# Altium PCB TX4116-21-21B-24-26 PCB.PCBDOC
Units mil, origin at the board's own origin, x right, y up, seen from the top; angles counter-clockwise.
Board outline 1900 x 1181.1 mil, 2 copper layers (Top Layer, Bottom Layer); 23 components, 16 nets, 59 pads, 153 vias.
Unrouted connection lines stored in the file: 3.
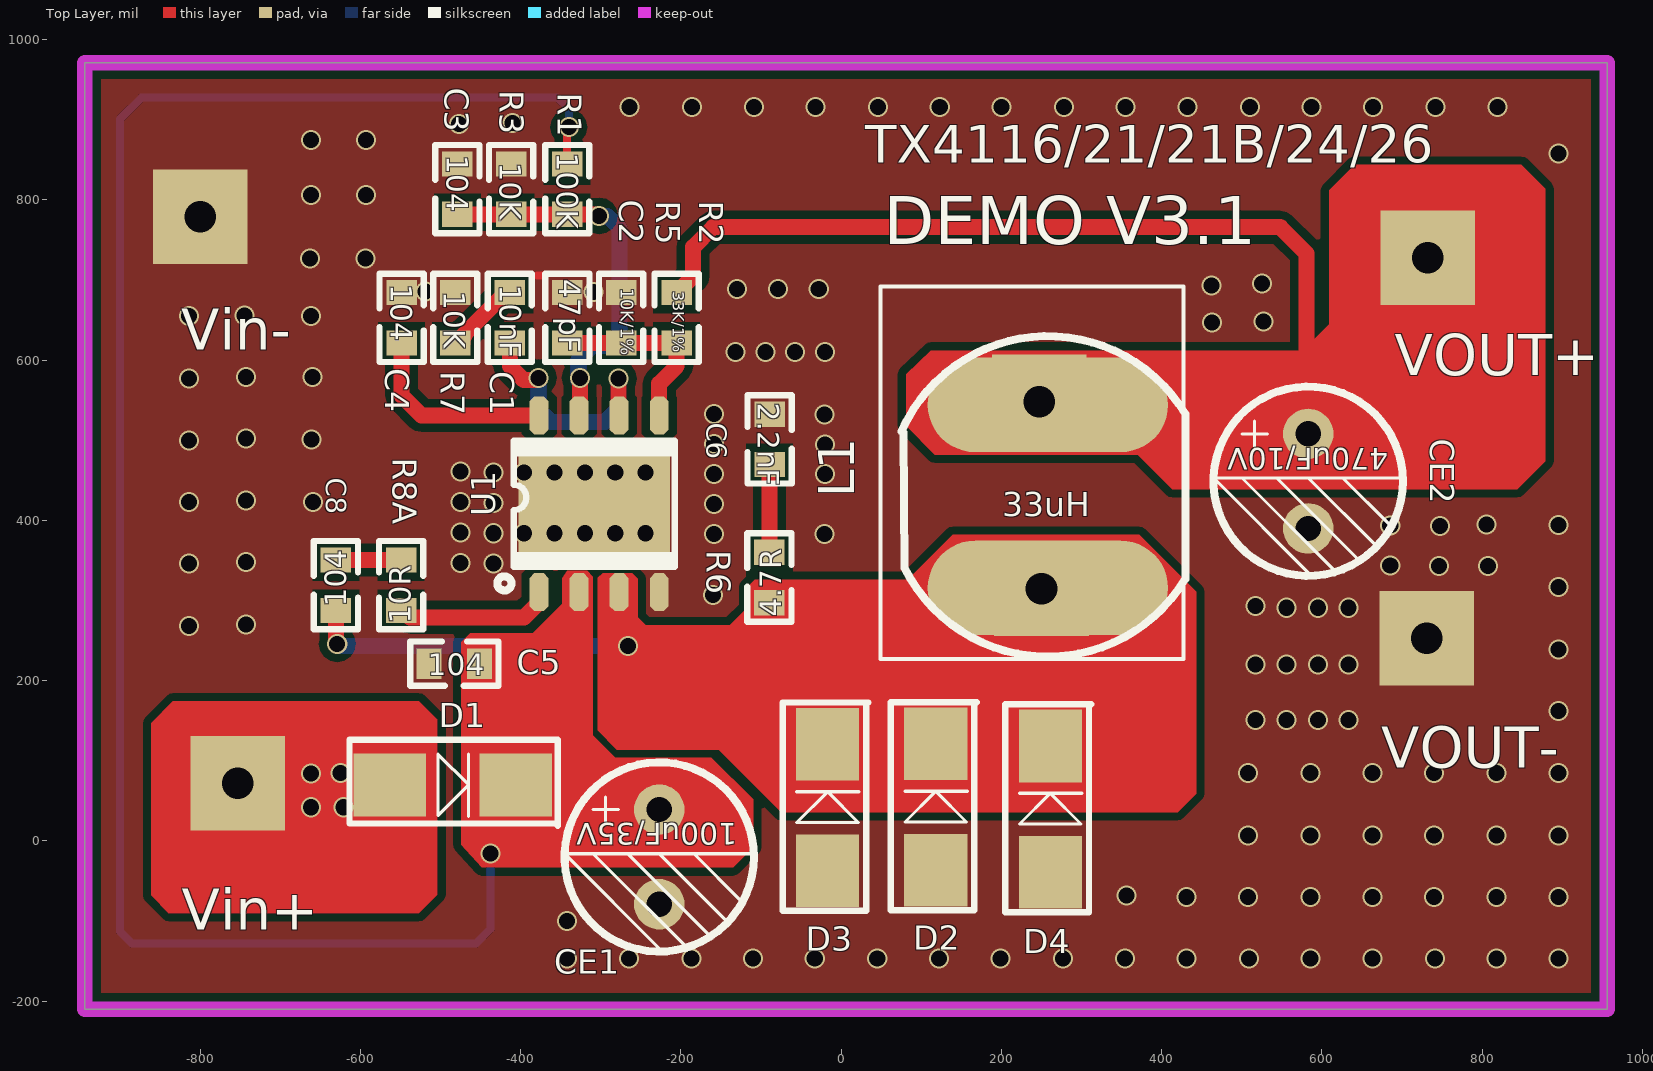
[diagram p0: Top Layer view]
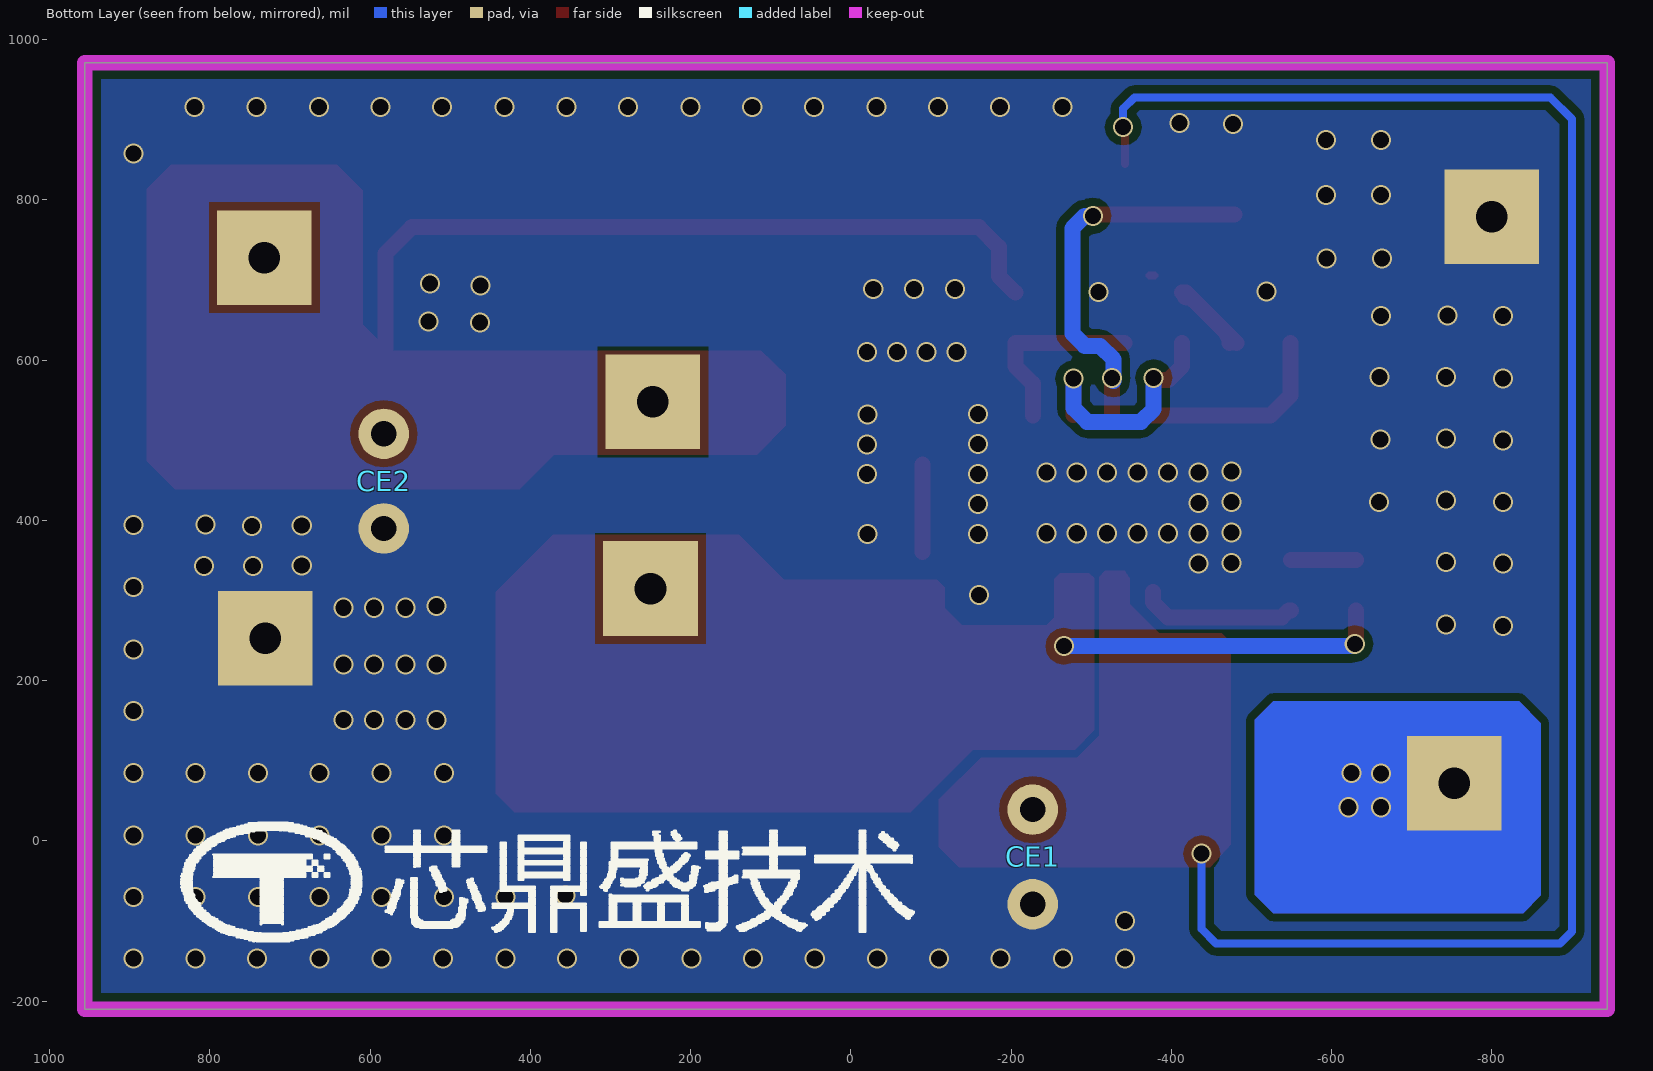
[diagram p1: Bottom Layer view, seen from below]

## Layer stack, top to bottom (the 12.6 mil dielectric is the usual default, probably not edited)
Top Layer: signal copper 1.4
Dielectric: dielectric 12.6, FR-4, Dk 4.8
Bottom Layer: signal copper 1.4

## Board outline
-944,-210 956,-210 956,971.1 -944,971.1

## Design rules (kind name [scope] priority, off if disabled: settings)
Clearance [All] p1: gap=10
PlaneConnect [All] p1: planeconnectstyle=NoConnect reliefexpansion=20 reliefentries=4 reliefconductorwidth=10 reliefairgap=10
PolygonConnect [All] p1: connectstyle=Direct reliefconductorwidth=0 reliefentries=4 polygonreliefangle="90 Angle"
RoutingVias [All] p1: holewidth=28 width=50 viastyle="Through Hole" minholewidth=28 minwidth=50 maxholewidth=28 maxwidth=50
SilkscreenOverComponentPads SilkToSolderMaskClearance [IsPad] p1: minsilkscreentomaskgap=10
SolderMaskExpansion [All] p1: expansion=4
TestPointUsage [All] p1: valid=0 allowmultiple=FALSE
Testpoint [All] p1: side=3 testpointundercomponent=TRUE minsize=40 maxsize=100 preferedsize=60 minholesize=0 maxholesize=40 preferedholesize=32 testpointgrid=1 style=297 order=0-112345678
Width [All] p1: maxlimit=100 minlimit=10 preferedwidth=10
22 further rules are at their usual default settings.

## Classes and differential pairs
component class 6321&8321&6322&8322: R6

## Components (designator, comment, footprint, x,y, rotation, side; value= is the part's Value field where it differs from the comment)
C1 "10nF" 0603 -419,648 r90 top (schematic designator C7)
C2 "47pF" 0603 -347,648 r90 top (schematic designator C6)
C3 "104" 0603 -484.35,808.66 r90 top (schematic designator C7)
C4 "104" 0603 -554,648 r90 top (schematic designator C7)
C5 "104" 0603 -478,216 r180 top (schematic designator C2)
C6 "2.2nF" 0603 -84,506 r270 top (schematic designator C5)
C8 "104" 0603 -636,314.31 r90 top (schematic designator C5)
CE1 "100uF/35V" C6 -239,-7 r270 bottom (schematic designator C1)
CE2 "470uF/10V" C6 571,462 r270 bottom (schematic designator C3)
D1 "Cap Semi" SMA -563.45,70 r0 top (schematic designator C4)
D2 "Cap Semi" SMA 118,-36.45 r90 top (schematic designator C4)
D3 "Cap Semi" SMA -17,-37 r90 top (schematic designator C4)
D4 "Cap Semi" SMA 261,-39 r90 top (schematic designator C4)
L1 "" CD105 258,430 r180 top
R1 "100K" 0603 -347.35,808.66 r90 top (schematic designator R3)
R2 "33K/1%" 0603 -200,657.69 r270 top (schematic designator R1)
R3 "10K" 0603 -417.35,808.66 r90 top
R5 "10K/1%" 0603 -280,648 r90 top (schematic designator R2)
R6 "4.7R" 0603 -95,324 r90 top (schematic designator R4)
R7 "10K" 0603 -487,648 r90 top (schematic designator R3)
R8A "10R" 0603 -544,324 r270 top (schematic designator R5)
U1 "TX4116/21/21B/24/26" ESOP-8A -312,413 r90 top
? "Comment" LOGO 722.33,-31 r180 bottom

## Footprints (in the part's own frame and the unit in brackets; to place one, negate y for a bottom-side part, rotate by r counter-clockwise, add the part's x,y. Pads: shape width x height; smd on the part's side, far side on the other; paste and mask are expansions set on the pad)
0603 [mm]
  rect 0.8x0.965 smd: 1(0.923,-0.136) 2(-0.677,-0.136)
  silkscreen extent -1.28,-0.84 1.52,0.56
C6 [mm]
  round 1.6 hole 0.8: 1(-1.17,-0.303) 2(1.83,-0.303)
CD105 [mm]
  oval 7.62x3 smd: 1(0,-2.9) 2(0,2.9)
  silkscreen extent -4.36,-5.08 4.64,5.08
ESOP-8A [mm]
  oct 1.2x0.6 smd: 1(-2.603,1.654) 2(-2.603,0.384) 3(-2.603,-0.886) 4(-2.603,-2.156) 5(2.997,-2.156) 6(2.997,-0.886) 7(2.997,0.384) 8(2.997,1.654)
  rect 3.048x4.8 smd: ""(0.2,-0.1)
  silkscreen extent -2.55,-2.65 2.2,2.98
LOGO [mil]
  silkscreen extent -113,-94 801,54
SMA [mm]
  rect 2.3x2 smd: 1(0,0) 2(4,0)
  silkscreen extent -1.28,-1.3 5.33,1.43

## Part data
C1 C2 C3 C4 C5 C6 C8: library part "Cap Semi", "Capacitor (Semiconductor SIM Model)"
CE1 CE2: library part "Cap Pol3", "Polarized Capacitor (Surface Mount)"
D1 D2 D3 D4: "Capacitor (Semiconductor SIM Model)"
L1: library part INDUCTOR
R1 R2 R3 R5 R6 R7 R8A: library part "Res Semi", "Semiconductor Resistor"
U1: library part PL6321

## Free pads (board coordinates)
  rect 118.11x118.11 hole 39.37: 0(-800,779) 0(-753,72) 0(247,548) 0(250,315) 0(731,253) 0(732,728)
  round 70.87 hole 39.37: 0(247,548) 1(250,315)

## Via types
v1: diameter 25, hole 20, Top Layer to Bottom Layer, tented both sides, 152 vias
v2: diameter 25/25 (per signal layer), hole 20, Top Layer to Bottom Layer, tented both sides, 1 vias

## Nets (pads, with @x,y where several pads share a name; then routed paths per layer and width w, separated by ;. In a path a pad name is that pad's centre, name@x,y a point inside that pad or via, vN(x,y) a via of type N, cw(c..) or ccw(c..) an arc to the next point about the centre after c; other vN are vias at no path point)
12V: D1.1 pad.0@-753,72
  other v1: -662,42 -621,42 -662,84 -625,85
EN: C3.2 R1.2 R3.2 U1.7 | length 475.8
  Top Layer w20: C3.2 R3.2 R1.2 v1@-304.01,782.01 ; U1.7@-326,532.11 v1(-326,578)
  Bottom Layer w20: v1@-328,574 -328,578 -328,601 -311,618 -292,618 -276.5,633.5 -276.5,764.5 -292,780 v1(-302,780)
GND: C2.1 C3.1 C4.1 C5.1 C6.2 CE1.2 CE2.2 D2.1 D3.1 D4.1 pad.0@731,253 pad.0@-800,779 R3.1 R5.1 R7.1 U1. U1.4 | length 6.3
  Top Layer w10: -379.35,706 -373,706
  other v1: -342,-147 -265,-147 -187,-147 -110,-147 -33,-147 45,-147 122,-147 199,-147 277,-147 354,-147 431,-147 509,-147 586,-147 663,-147 741,-147 818,-147 895,-147 -342,-100 431,-70 508,-70 586,-70 663,-70 740,-70 818,-70 895,-70 356,-68 508,7 586,7 663,7 740,7 818,7 895,7 508,85 586,85 663,85 740,85 818,85 895,85 517,151 556,151 595,151 633,151 895,162 517,220 556,220 595,220 633,220 895,239 -814,268 -743,270 556,291 595,291 633,291 517,293 -160,307 895,317 746.29,342.89 807.29,342.89 685.29,343.89 -814,346 -434,346 -475,347 -743,348 -159,383 -21,383 -434,384 -396,384 -358,384 -320,384 -282,384 -244,384 -475,385 747.29,392.89 685.29,393.89 895,394 805.29,394.89 -159,420.5 -434,422 -814,423 -659,423 -475,423 -743,425 -159,458 -20,458 -434,460 -396,460 -358,460 -320,460 -282,460 -244,460 -475,461 -159,495.5 -20,495 -814,500 -661,501 -743,502 -21,532 -159,533 -814,577 -743,579 -660,579 -132,610 -94.75,610 -57.5,610 -20.25,610 463,647 527,648 -814,655 -662,655 -309,685 -519,686 -130,689 -79,689 -28,689 462,693 525,696 -663,727 -594,727 -662,806 -593,806 895,858 -662,875 -593,875 -477,895 -410,896 -264,916 -186,916 -109,916 -32,916 46,916 123,916 200,916 278,916 355,916 432,916 510,916 587,916 664,916 742,916 819,916
  other v2: -745,656
NetC1_1: C5.2 CE1.1 D1.2 R1.1 U1.2 | length 2503.5
  Top Layer w10: R1.1 v1@-342,889
  Top Layer w35: D1.2@-402.81,64.8 -402.81,70 -402.81,191.19 -328,266 U1.2@-328,309.64
  Bottom Layer w10: v1(-438,-16) -438,-110 -456,-128 -885,-128 -900,-113 -900,901 -873,928 -354,928 -340,914 v1(-340,891)
NetC3_1: CE2.1 L1.1 pad.0@247,548 pad.0@250,315 pad.0@732,728 R2.2 | length 1080.9
  Top Layer w20: R2.2 -184.94,704.75 -184.94,741.06 -160,766 548,766 581,733 581,509.99 CE2.1
NetC5_1: C8.1 R8A.2 | length 81.3
  Top Layer w20: C8.1 R8A.2
NetC5_2: C8.2 D2.2 D3.2 D4.2 L1.2 pad.1 R6.2 U1.3 | length 404.3
  Top Layer w20: v1@-630.65,247.65 C8.2
  Bottom Layer w20: v1(-629,246) -626,243 v1(-266,243)
NetC6_2: C2.2 R2.1 R5.2 U1.5 | length 235.7
  Top Layer w20: C2.2 R5.2 R2.1 -205.35,592.65 -227.12,570.88 U1.5
NetC7_2: C4.2 U1.8 | length 247.4
  Top Layer w20: C4.2 -548.65,555.65 -523.99,530.99 U1.8
NetLED_1: 
NetR3_2: C1.1 R7.2 | length 125.2
  Top Layer w20: R7.2 -418.62,684.34 C1.1 ; R7.2@-472.65,621.35 cw(c-451.02,621.35) R7.2@-466.31,636.64 ; C1.1@-429.65,673.31 cw(c-416.89,660.55) C1.1@-416.89,678.59
NetR5_1: R8A.1 U1.1 | length 196.2
  Top Layer w20: R8A.1 -546.68,287.66 -538.13,279.12 -395.88,279.12 -377.12,297.88 U1.1
NetR6_1: C6.1 R6.1 | length 109.4
  Top Layer w20: R6.1 -89.65,469.37 C6.1
NetR7_2: 
U1-6: C1.2 U1.6 | length 307.7
  Top Layer w20: C1.2 -413.65,592.65 -396,575 -381,575 v1(-378,578) ; U1.6@-278,531.87 v1(-278,577)
  Bottom Layer w20: v1(-378,578) -378,539 -362,523 -295,523 -278,540 v1(-278,577)
USB-6: 

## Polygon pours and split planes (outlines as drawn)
GND on Top Layer "Top Layer-No Net" (solid, remove dead copper, pour order 1009): 946,-200 946,955 956,965 951,960 -944,960 -944,-210 956,-210
GND on Bottom Layer "Top Layer-No Net" (solid, remove dead copper, pour order 1009): 955,-200 955,955 965,965 960,960 -935,960 -935,-210 965,-210

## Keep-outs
Keep-Out Layer:
  the board outline again, w19.68

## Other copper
Top Layer:
  region net NetC5_2: -297.89,334 -261,334 -254,327 -254,279 -244,269 -139,269 -117.2,290.8 -117.2,316.8 -108,326 83,326 139,382 372,382 443,311 443,59 420,36 -75,36 -153,114 -280,114 -304,138 -304,328.63
  region: 111.73,612 576,612 609,645 609,812 641,844 849,844 879,814 879,474 844,439 413,439 370,482 117,482 81,518 81,582.41
  region net 12V: -834,174 -527,174 -504,151 -504,-67 -527,-90 -839,-90 -861,-68 -861,147
  region net NetC1_1: -341.71,337 -317,337 -310,330 -310,132 -282,104 -162,104 -110,52 -110,-8 -135,-33 -448.48,-33 -474,-4.75 -474,248 -463,259 -385,259 -348.2,295.8 -348,328
Bottom Layer:
  region net 12V: -834,174 -527,174 -504,151 -504,-67 -527,-90 -839,-90 -861,-68 -861,147

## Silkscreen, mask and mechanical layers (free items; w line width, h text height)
Top Overlay:
  lines w5: 49,227 427,227 427,692 49,692 49,227
  text "DEMO V3.1" at 53,745 h60
  text "Vin-" at -824,613 h51.18
  text "VOUT+" at 691,581 h51.18
  text "33uH" at 201,405 h30
  text "VOUT-" at 674,91 h51.18
  text "Vin+" at -823,-111 h51.18
Bottom Solder:
  region: -386,474 -386,368 -222,368 -222,474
